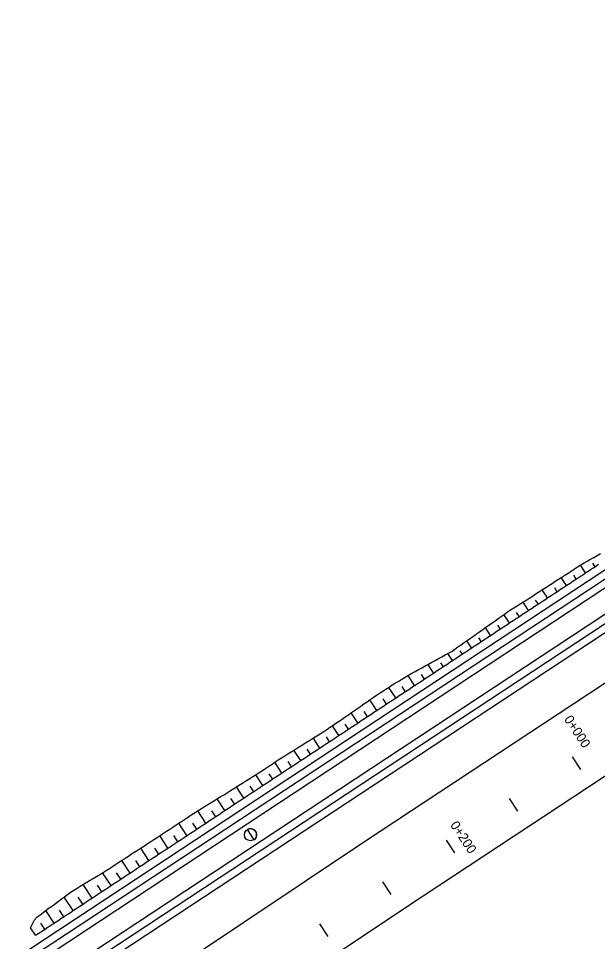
# Model space of a CAD drawing. Extents: x 6503541 to 6503743, y 5888004 to 5888145.
# Drawn here: x 6503596.703 to 6503598.537, y 5888050.855 to 5888053.781 of the extents above; entities that cross this region are included whole.
import ezdxf

# ---------------------------------------------------------------- set-up
doc = ezdxf.new("R2010")
doc.units = 0
doc.layers.add('12', color=7, linetype='Continuous')

msp = doc.modelspace()

# ---------------------------------------------------------------- linework, layer by layer
at = {"layer": '12'}
for p, q in [((6503592.6202, 5888048.0879), (6503601.3481, 5888053.842)), ((6503592.6334, 5888048.0679), (6503601.3614, 5888053.822)), ((6503592.6717, 5888048.0098), (6503601.3997, 5888053.7639)), ((6503592.6849, 5888047.9897), (6503601.4129, 5888053.7438)), ((6503596.6916, 5888050.8008), (6503600.0814, 5888053.0357)), ((6503596.8173, 5888050.6854), (6503599.6574, 5888052.5577)), ((6503598.4991, 5888052.0235), (6503598.4831, 5888052.0478)), ((6503598.5217, 5888052.0547), (6503598.5292, 5888052.0433)), ((6503598.439, 5888051.9839), (6503598.4225, 5888052.009)), ((6503598.4609, 5888052.0161), (6503598.4691, 5888052.0037)), ((6503599.4945, 5888051.9945), (6503597.9384, 5888050.9686)), ((6503598.4006, 5888051.9768), (6503598.409, 5888051.9641)), ((6503598.3789, 5888051.9443), (6503598.362, 5888051.9699)), ((6503598.3188, 5888051.9046), (6503598.3016, 5888051.9308)), ((6503598.3403, 5888051.9374), (6503598.3489, 5888051.9245)), ((6503598.9165, 5888051.9081), (6503597.8024, 5888051.1736)), ((6503598.2587, 5888051.865), (6503598.241, 5888051.8918)), ((6503598.2796, 5888051.8986), (6503598.2888, 5888051.8848)), ((6503598.1986, 5888051.8254), (6503598.1822, 5888051.8502)), ((6503598.2201, 5888051.8581), (6503598.2286, 5888051.8452)), ((6503598.1385, 5888051.7857), (6503598.1234, 5888051.8086)), ((6503598.1607, 5888051.8175), (6503598.1685, 5888051.8056)), ((6503598.1012, 5888051.7769), (6503598.1084, 5888051.7659)), ((6503598.0784, 5888051.7461), (6503598.0637, 5888051.7684)), ((6503598.0182, 5888051.7065), (6503598.0002, 5888051.7339)), ((6503598.0401, 5888051.7387), (6503598.0483, 5888051.7263)), ((6503597.9581, 5888051.6669), (6503597.9371, 5888051.6987)), ((6503597.9783, 5888051.7016), (6503597.9882, 5888051.6867)), ((6503597.898, 5888051.6272), (6503597.8757, 5888051.6611)), ((6503597.9172, 5888051.6635), (6503597.9281, 5888051.647)), ((6503597.8379, 5888051.5876), (6503597.8158, 5888051.6212)), ((6503597.8568, 5888051.6244), (6503597.868, 5888051.6074)), ((6503597.7778, 5888051.548), (6503597.7566, 5888051.5802)), ((6503597.797, 5888051.5842), (6503597.8079, 5888051.5678)), ((6503597.7177, 5888051.5083), (6503597.6974, 5888051.5391)), ((6503597.7374, 5888051.5439), (6503597.7477, 5888051.5281)), ((6503597.6576, 5888051.4687), (6503597.6367, 5888051.5004)), ((6503597.6774, 5888051.504), (6503597.6876, 5888051.4885)), ((6503597.5975, 5888051.4291), (6503597.5757, 5888051.4622)), ((6503597.6169, 5888051.4651), (6503597.6275, 5888051.4489)), ((6503597.5374, 5888051.3894), (6503597.5148, 5888051.4236)), ((6503597.5563, 5888051.4262), (6503597.5674, 5888051.4093)), ((6503597.4772, 5888051.3498), (6503597.4546, 5888051.3841)), ((6503597.4961, 5888051.3866), (6503597.5073, 5888051.3696)), ((6503597.4171, 5888051.3102), (6503597.3938, 5888051.3456)), ((6503597.4357, 5888051.3474), (6503597.4472, 5888051.33)), ((6503597.357, 5888051.2705), (6503597.3327, 5888051.3075)), ((6503597.3752, 5888051.3083), (6503597.3871, 5888051.2904)), ((6503597.2969, 5888051.2309), (6503597.2711, 5888051.27)), ((6503597.3144, 5888051.2698), (6503597.327, 5888051.2507)), ((6503597.2368, 5888051.1913), (6503597.211, 5888051.2305)), ((6503597.2539, 5888051.2307), (6503597.2669, 5888051.2111)), ((6503597.1767, 5888051.1517), (6503597.1508, 5888051.191)), ((6503597.1938, 5888051.1911), (6503597.2067, 5888051.1715)), ((6503597.8024, 5888051.1736), (6503597.1016, 5888050.7056)), ((6503597.1166, 5888051.112), (6503597.0905, 5888051.1515)), ((6503597.1336, 5888051.1515), (6503597.1466, 5888051.1318)), ((6503597.0565, 5888051.0724), (6503597.0301, 5888051.1124)), ((6503597.0734, 5888051.1121), (6503597.0865, 5888051.0922)), ((6503596.9963, 5888051.0328), (6503596.9696, 5888051.0733)), ((6503597.0131, 5888051.0727), (6503597.0264, 5888051.0526)), ((6503596.9362, 5888050.9931), (6503596.9078, 5888051.0362)), ((6503596.9525, 5888051.0338), (6503596.9663, 5888051.013)), ((6503596.8761, 5888050.9535), (6503596.8478, 5888050.9965)), ((6503596.8916, 5888050.9955), (6503596.9062, 5888050.9733)), ((6503596.816, 5888050.9139), (6503596.7899, 5888050.9535)), ((6503596.8324, 5888050.9544), (6503596.8461, 5888050.9337)), ((6503597.9384, 5888050.9686), (6503597.5578, 5888050.7145)), ((6503596.7734, 5888050.9131), (6503596.786, 5888050.8941))]:
    msp.add_line(p, q, dxfattribs=at)
for points in [[(6503596.7573, 5888050.8752), (6503596.7416, 5888050.899), (6503596.7477, 5888050.9115), (6503596.754, 5888050.9238), (6503596.762, 5888050.9334), (6503596.7718, 5888050.9404), (6503596.7816, 5888050.9474), (6503596.7912, 5888050.9545), (6503596.8009, 5888050.9617), (6503596.8105, 5888050.9688), (6503596.8202, 5888050.976), (6503596.8298, 5888050.9832), (6503596.8395, 5888050.9903), (6503596.8491, 5888050.9975), (6503596.8588, 5888051.0047), (6503596.8684, 5888051.0118), (6503596.8783, 5888051.0186), (6503596.8886, 5888051.0248), (6503596.8989, 5888051.0309), (6503596.9093, 5888051.0371), (6503596.9196, 5888051.0432), (6503596.9299, 5888051.0494), (6503596.9402, 5888051.0555), (6503596.9505, 5888051.0617), (6503596.9608, 5888051.0679), (6503596.971, 5888051.0742), (6503596.9811, 5888051.0807), (6503596.9912, 5888051.0872), (6503597.0013, 5888051.0937), (6503597.0114, 5888051.1002), (6503597.0214, 5888051.1067), (6503597.0315, 5888051.1133), (6503597.0416, 5888051.1198), (6503597.0517, 5888051.1263), (6503597.0617, 5888051.1328), (6503597.0718, 5888051.1393), (6503597.0819, 5888051.1459), (6503597.0919, 5888051.1524), (6503597.102, 5888051.159), (6503597.112, 5888051.1656), (6503597.122, 5888051.1722), (6503597.1321, 5888051.1787), (6503597.1421, 5888051.1853), (6503597.1522, 5888051.1919), (6503597.1622, 5888051.1985), (6503597.1722, 5888051.205), (6503597.1823, 5888051.2116), (6503597.1923, 5888051.2182), (6503597.2023, 5888051.2248), (6503597.2124, 5888051.2314), (6503597.2224, 5888051.238), (6503597.2324, 5888051.2446), (6503597.2424, 5888051.2512), (6503597.2525, 5888051.2578), (6503597.2625, 5888051.2643), (6503597.2725, 5888051.2709), (6503597.2826, 5888051.2774), (6503597.2929, 5888051.2836), (6503597.3032, 5888051.2898), (6503597.3135, 5888051.296), (6503597.3238, 5888051.3022), (6503597.3341, 5888051.3084), (6503597.3444, 5888051.3146), (6503597.3547, 5888051.3208), (6503597.3648, 5888051.3272), (6503597.3749, 5888051.3336), (6503597.3851, 5888051.34), (6503597.3952, 5888051.3464), (6503597.4053, 5888051.3529), (6503597.4155, 5888051.3593), (6503597.4256, 5888051.3657), (6503597.4357, 5888051.3722), (6503597.4459, 5888051.3786), (6503597.456, 5888051.385), (6503597.4661, 5888051.3915), (6503597.4763, 5888051.3979), (6503597.4864, 5888051.4044), (6503597.4963, 5888051.4111), (6503597.5063, 5888051.4178), (6503597.5162, 5888051.4245), (6503597.5262, 5888051.4312), (6503597.5364, 5888051.4376), (6503597.5465, 5888051.4439), (6503597.5567, 5888051.4503), (6503597.5669, 5888051.4567), (6503597.5771, 5888051.463), (6503597.5872, 5888051.4694), (6503597.5974, 5888051.4758), (6503597.6076, 5888051.4821), (6503597.6178, 5888051.4885), (6503597.6279, 5888051.4949), (6503597.6381, 5888051.5012), (6503597.6483, 5888051.5076), (6503597.6585, 5888051.514), (6503597.6686, 5888051.5203), (6503597.6788, 5888051.5267), (6503597.6889, 5888051.5333), (6503597.6987, 5888051.5401), (6503597.7086, 5888051.5469), (6503597.7185, 5888051.5538), (6503597.7283, 5888051.5606), (6503597.7382, 5888051.5674), (6503597.7481, 5888051.5743), (6503597.7579, 5888051.5811), (6503597.7678, 5888051.588), (6503597.7777, 5888051.5948), (6503597.7875, 5888051.6016), (6503597.7974, 5888051.6085), (6503597.8073, 5888051.6153), (6503597.8171, 5888051.6221), (6503597.827, 5888051.629), (6503597.837, 5888051.6357), (6503597.847, 5888051.6423), (6503597.857, 5888051.6489), (6503597.867, 5888051.6554), (6503597.8771, 5888051.662), (6503597.8872, 5888051.6685), (6503597.8975, 5888051.6747), (6503597.9077, 5888051.6809), (6503597.918, 5888051.6871), (6503597.9283, 5888051.6934), (6503597.9386, 5888051.6996), (6503597.9488, 5888051.7058), (6503597.9594, 5888051.7116), (6503597.9699, 5888051.7174), (6503597.9805, 5888051.7231), (6503597.9911, 5888051.7289), (6503598.0017, 5888051.7347), (6503598.0122, 5888051.7404), (6503598.0228, 5888051.7462), (6503598.0334, 5888051.7519), (6503598.044, 5888051.7577), (6503598.0545, 5888051.7635), (6503598.0651, 5888051.7692), (6503598.0757, 5888051.775), (6503598.0855, 5888051.7819), (6503598.0953, 5888051.7888), (6503598.1051, 5888051.7957), (6503598.1149, 5888051.8027), (6503598.1247, 5888051.8096), (6503598.1345, 5888051.8165), (6503598.1443, 5888051.8235), (6503598.1541, 5888051.8304), (6503598.1639, 5888051.8373), (6503598.1737, 5888051.8443), (6503598.1836, 5888051.8512), (6503598.1934, 5888051.8581), (6503598.2032, 5888051.8651), (6503598.213, 5888051.872), (6503598.2228, 5888051.8789), (6503598.2326, 5888051.8859), (6503598.2424, 5888051.8928), (6503598.2522, 5888051.8997), (6503598.262, 5888051.9067), (6503598.2719, 5888051.9134), (6503598.2824, 5888051.9193), (6503598.2928, 5888051.9253), (6503598.303, 5888051.9317), (6503598.313, 5888051.9382), (6503598.3231, 5888051.9447), (6503598.3332, 5888051.9512), (6503598.3433, 5888051.9578), (6503598.3534, 5888051.9643), (6503598.3634, 5888051.9708), (6503598.3735, 5888051.9773), (6503598.3836, 5888051.9838), (6503598.3937, 5888051.9904), (6503598.4037, 5888051.9969), (6503598.4138, 5888052.0034), (6503598.4239, 5888052.0099), (6503598.434, 5888052.0164), (6503598.444, 5888052.0229), (6503598.4541, 5888052.0295), (6503598.4642, 5888052.036), (6503598.4743, 5888052.0424), (6503598.4845, 5888052.0487), (6503598.4947, 5888052.0551), (6503598.5051, 5888052.061), (6503598.5156, 5888052.067), (6503598.5261, 5888052.0729), (6503598.5366, 5888052.0788), (6503598.5471, 5888052.0847)], [(6503596.7573, 5888050.8752), (6503596.7673, 5888050.8818), (6503596.7773, 5888050.8884), (6503596.7873, 5888050.895), (6503596.7974, 5888050.9016), (6503596.8074, 5888050.9082), (6503596.8174, 5888050.9148), (6503596.8274, 5888050.9214), (6503596.8374, 5888050.928), (6503596.8474, 5888050.9346), (6503596.8575, 5888050.9412), (6503596.8675, 5888050.9478), (6503596.8775, 5888050.9544), (6503596.8875, 5888050.961), (6503596.8975, 5888050.9677), (6503596.9076, 5888050.9743), (6503596.9176, 5888050.9809), (6503596.9276, 5888050.9875), (6503596.9376, 5888050.9941), (6503596.9476, 5888051.0007), (6503596.9577, 5888051.0073), (6503596.9677, 5888051.0139), (6503596.9777, 5888051.0205), (6503596.9877, 5888051.0271), (6503596.9977, 5888051.0337), (6503597.0077, 5888051.0403), (6503597.0178, 5888051.0469), (6503597.0278, 5888051.0535), (6503597.0378, 5888051.0601), (6503597.0478, 5888051.0667), (6503597.0578, 5888051.0733), (6503597.0679, 5888051.0799), (6503597.0779, 5888051.0865), (6503597.0879, 5888051.0931), (6503597.0979, 5888051.0998), (6503597.1079, 5888051.1064), (6503597.118, 5888051.113), (6503597.128, 5888051.1196), (6503597.138, 5888051.1262), (6503597.148, 5888051.1328), (6503597.158, 5888051.1394), (6503597.168, 5888051.146), (6503597.1781, 5888051.1526), (6503597.1881, 5888051.1592), (6503597.1981, 5888051.1658), (6503597.2081, 5888051.1724), (6503597.2181, 5888051.179), (6503597.2282, 5888051.1856), (6503597.2382, 5888051.1922), (6503597.2482, 5888051.1988), (6503597.2582, 5888051.2054), (6503597.2682, 5888051.212), (6503597.2782, 5888051.2186), (6503597.2883, 5888051.2252), (6503597.2983, 5888051.2319), (6503597.3083, 5888051.2385), (6503597.3183, 5888051.2451), (6503597.3283, 5888051.2517), (6503597.3384, 5888051.2583), (6503597.3484, 5888051.2649), (6503597.3584, 5888051.2715), (6503597.3684, 5888051.2781), (6503597.3784, 5888051.2847), (6503597.3885, 5888051.2913), (6503597.3985, 5888051.2979), (6503597.4085, 5888051.3045), (6503597.4185, 5888051.3111), (6503597.4285, 5888051.3177), (6503597.4385, 5888051.3243), (6503597.4486, 5888051.3309), (6503597.4586, 5888051.3375), (6503597.4686, 5888051.3441), (6503597.4786, 5888051.3507), (6503597.4886, 5888051.3573), (6503597.4987, 5888051.364), (6503597.5087, 5888051.3706), (6503597.5187, 5888051.3772), (6503597.5287, 5888051.3838), (6503597.5387, 5888051.3904), (6503597.5488, 5888051.397), (6503597.5588, 5888051.4036), (6503597.5688, 5888051.4102), (6503597.5788, 5888051.4168), (6503597.5888, 5888051.4234), (6503597.5988, 5888051.43), (6503597.6089, 5888051.4366), (6503597.6189, 5888051.4432), (6503597.6289, 5888051.4498), (6503597.6389, 5888051.4564), (6503597.6489, 5888051.463), (6503597.659, 5888051.4696), (6503597.669, 5888051.4762), (6503597.679, 5888051.4828), (6503597.689, 5888051.4894), (6503597.699, 5888051.4961), (6503597.7091, 5888051.5027), (6503597.7191, 5888051.5093), (6503597.7291, 5888051.5159), (6503597.7391, 5888051.5225), (6503597.7491, 5888051.5291), (6503597.7591, 5888051.5357), (6503597.7692, 5888051.5423), (6503597.7792, 5888051.5489), (6503597.7892, 5888051.5555), (6503597.7992, 5888051.5621), (6503597.8092, 5888051.5687), (6503597.8193, 5888051.5753), (6503597.8293, 5888051.5819), (6503597.8393, 5888051.5885), (6503597.8493, 5888051.5951), (6503597.8593, 5888051.6017), (6503597.8694, 5888051.6083), (6503597.8794, 5888051.6149), (6503597.8894, 5888051.6215), (6503597.8994, 5888051.6282), (6503597.9094, 5888051.6348), (6503597.9194, 5888051.6414), (6503597.9295, 5888051.648), (6503597.9395, 5888051.6546), (6503597.9495, 5888051.6612), (6503597.9595, 5888051.6678), (6503597.9695, 5888051.6744), (6503597.9796, 5888051.681), (6503597.9896, 5888051.6876), (6503597.9996, 5888051.6942), (6503598.0096, 5888051.7008), (6503598.0196, 5888051.7074), (6503598.0296, 5888051.714), (6503598.0397, 5888051.7206), (6503598.0497, 5888051.7272), (6503598.0597, 5888051.7338), (6503598.0697, 5888051.7404), (6503598.0797, 5888051.747), (6503598.0898, 5888051.7536), (6503598.0998, 5888051.7603), (6503598.1098, 5888051.7669), (6503598.1198, 5888051.7735), (6503598.1298, 5888051.7801), (6503598.1399, 5888051.7867), (6503598.1499, 5888051.7933), (6503598.1599, 5888051.7999), (6503598.1699, 5888051.8065), (6503598.1799, 5888051.8131), (6503598.1899, 5888051.8197), (6503598.2, 5888051.8263), (6503598.21, 5888051.8329), (6503598.22, 5888051.8395), (6503598.23, 5888051.8461), (6503598.24, 5888051.8527), (6503598.2501, 5888051.8593), (6503598.2601, 5888051.8659), (6503598.2701, 5888051.8725), (6503598.2801, 5888051.8791), (6503598.2901, 5888051.8857), (6503598.3002, 5888051.8924), (6503598.3102, 5888051.899), (6503598.3202, 5888051.9056), (6503598.3302, 5888051.9122), (6503598.3402, 5888051.9188), (6503598.3502, 5888051.9254), (6503598.3603, 5888051.932), (6503598.3703, 5888051.9386), (6503598.3803, 5888051.9452), (6503598.3903, 5888051.9518), (6503598.4003, 5888051.9584), (6503598.4104, 5888051.965), (6503598.4204, 5888051.9716), (6503598.4304, 5888051.9782), (6503598.4404, 5888051.9848), (6503598.4504, 5888051.9914), (6503598.4605, 5888051.998), (6503598.4705, 5888052.0046), (6503598.4805, 5888052.0112), (6503598.4905, 5888052.0178), (6503598.5005, 5888052.0245), (6503598.5105, 5888052.0311), (6503598.5206, 5888052.0377), (6503598.5306, 5888052.0443), (6503598.5406, 5888052.0509)], [(6503598.485, 5888051.4008), (6503598.4586, 5888051.4409)], [(6503598.2846, 5888051.2687), (6503598.2582, 5888051.3088)], [(6503597.4277, 5888051.21), (6503597.4488, 5888051.1779)], [(6503598.0578, 5888051.1767), (6503598.0843, 5888051.1366)], [(6503597.8841, 5888051.0045), (6503597.8574, 5888051.0444)], [(6503597.6845, 5888050.8712), (6503597.6578, 5888050.9111)]]:
    msp.add_lwpolyline(points, dxfattribs=at)
msp.add_circle((6503597.4383, 5888051.1939), 0.0192, dxfattribs=at)
for start, end in [(358.9485, 123.3957), (303.3957, 358.9485)]:
    msp.add_arc((6503597.4383, 5888051.1939), 0.0192, start, end, dxfattribs=at)

# ---------------------------------------------------------------- texts
for s, p in [('0+000', (6503598.4302, 5888051.5598)), ('0+200', (6503598.0693, 5888051.2248))]:
    msp.add_text(s, height=0.03, rotation=303.3957, dxfattribs=at).set_placement(p)

doc.saveas('drawing.dxf')
